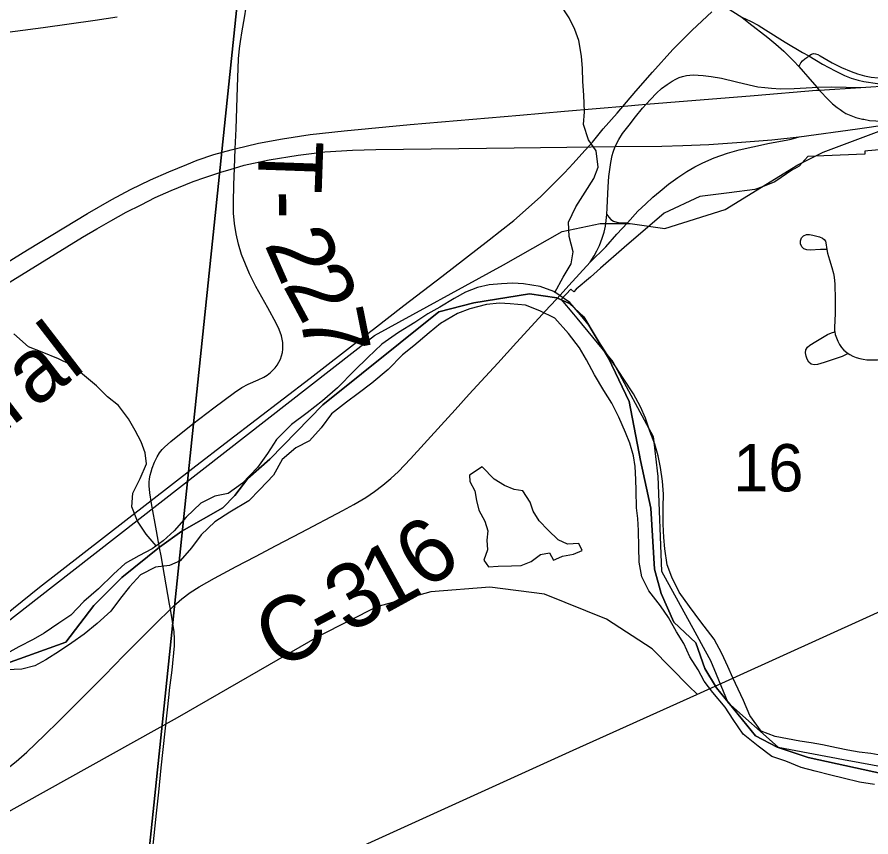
# Model space of a CAD drawing. Extents: x 0 to 34, y 0 to 22.
# Drawn here: x 5.966 to 6.722, y 17.371 to 18.097 of the extents above; entities that cross this region are included whole.
import ezdxf

# ---------------------------------------------------------------- set-up
doc = ezdxf.new("R2010")
doc.units = 0
for name, color, linetype in [('GM_X_City_Street', 7, 'Continuous'), ('GM_X_County_Road', 7, 'Continuous'), ('GM_X_County_Road_Text', 7, 'Continuous'), ('GM_X_Major_River', 7, 'Continuous'), ('GM_X_Minor_Lake', 7, 'Continuous'), ('GM_X_Minor_River', 7, 'Continuous'), ('GM_X_Rail_Line', 7, 'Continuous'), ('GM_X_Rail_Line_Text', 7, 'Continuous'), ('GM_X_Section', 7, 'Continuous'), ('GM_X_Section_Text', 7, 'Continuous'), ('GM_X_State_Route', 7, 'Continuous'), ('GM_X_Township_Road', 7, 'Continuous'), ('GM_X_Township_Road_Text', 7, 'Continuous'), ('GM_X_US_Route', 7, 'Continuous'), ('SC_Shading1', 7, 'Continuous')]:
    doc.layers.add(name, color=color, linetype=linetype)

msp = doc.modelspace()

# ---------------------------------------------------------------- linework, layer by layer
at = {"layer": 'GM_X_City_Street'}
for points in [[(6.68261, 17.89107), (6.67714, 17.89083), (6.6679, 17.89041), (6.66494, 17.89065), (6.66233, 17.8915), (6.66043, 17.8933), (6.65942, 17.8958), (6.65942, 17.89856), (6.66033, 17.90116), (6.6621, 17.90316), (6.66453, 17.90423), (6.66729, 17.90421), (6.67028, 17.90362), (6.67617, 17.90203), (6.67884, 17.90091), (6.6803, 17.89987), (6.68145, 17.89835)], [(6.68145, 17.89835), (6.68182, 17.89677), (6.68261, 17.89107)], [(6.68261, 17.89107), (6.68333, 17.88763), (6.68507, 17.88164), (6.68699, 17.87503), (6.68856, 17.86968), (6.68913, 17.86632), (6.68972, 17.86033), (6.69005, 17.84679), (6.68997, 17.83445), (6.68937, 17.82205), (6.68956, 17.81886), (6.68971, 17.81808)], [(5.94908, 17.52193), (6.00928, 17.54355), (6.034, 17.57598), (6.05869, 17.60068), (6.09198, 17.62754), (6.11197, 17.64165), (6.14824, 17.66245), (6.1588, 17.67338), (6.17022, 17.68824), (6.18965, 17.70538), (6.23654, 17.7534), (6.33939, 17.83572), (6.37026, 17.84374), (6.41941, 17.85174), (6.44369, 17.84821), (6.45506, 17.8432), (6.4677, 17.83122), (6.48945, 17.79478), (6.50784, 17.75636), (6.5177, 17.70429), (6.52683, 17.662), (6.53025, 17.60829), (6.53597, 17.58656), (6.54741, 17.56141), (6.56684, 17.54313), (6.57483, 17.52028), (6.58512, 17.50314), (6.61942, 17.46086), (6.63885, 17.45058), (6.66628, 17.44144), (6.74058, 17.42544)], [(6.74058, 17.42544), (6.66628, 17.44144), (6.63885, 17.45058), (6.61942, 17.46086), (6.58512, 17.50314), (6.57483, 17.52028), (6.56684, 17.54313), (6.54741, 17.56141), (6.53597, 17.58656), (6.53025, 17.60829), (6.52683, 17.662), (6.5177, 17.70429), (6.50784, 17.75636), (6.48945, 17.79478), (6.4677, 17.83122), (6.45506, 17.8432), (6.44369, 17.84821), (6.41941, 17.85174), (6.37026, 17.84374), (6.33939, 17.83572), (6.23654, 17.7534), (6.18965, 17.70538), (6.17022, 17.68824), (6.1588, 17.67338), (6.14824, 17.66245), (6.11197, 17.64165), (6.09198, 17.62754), (6.05869, 17.60068), (6.034, 17.57598), (6.00928, 17.54355), (5.94908, 17.52193)], [(6.70143, 17.79893), (6.69864, 17.79737), (6.69631, 17.79621), (6.68022, 17.79092), (6.67432, 17.78932), (6.67141, 17.78902), (6.66879, 17.78957), (6.6668, 17.79124), (6.6654, 17.79378), (6.66437, 17.7966), (6.66376, 17.79946), (6.66405, 17.80213), (6.66547, 17.8044), (6.66772, 17.80624), (6.67293, 17.80963), (6.68337, 17.81582), (6.68665, 17.81721), (6.68971, 17.81808)], [(6.68971, 17.81808), (6.69015, 17.81571), (6.69112, 17.81266), (6.69239, 17.80975), (6.6939, 17.80694), (6.69568, 17.80428), (6.69779, 17.80185), (6.70023, 17.79974), (6.70143, 17.79893)], [(6.70143, 17.79893), (6.7029, 17.79797), (6.70576, 17.79653), (6.70872, 17.79538), (6.71177, 17.7945), (6.71488, 17.79387), (6.71801, 17.79347), (6.72115, 17.79327), (6.72744, 17.7934), (6.72885, 17.79354)]]:
    msp.add_lwpolyline(points, dxfattribs=at)
at = {"layer": 'GM_X_County_Road'}
for points in [[(6.47331, 17.87963), (6.4769, 17.88537), (6.47915, 17.88962), (6.48147, 17.89441), (6.48393, 17.90108), (6.48557, 17.90628), (6.4867, 17.91149), (6.48748, 17.91644), (6.48789, 17.92179), (6.48834, 17.92774), (6.48913, 17.94634), (6.48983, 17.95561), (6.49146, 17.96789), (6.49266, 17.97397), (6.49351, 17.97696), (6.49545, 17.98197), (6.49576, 17.98275), (6.49859, 17.98828), (6.50192, 17.99353), (6.50763, 18.00089), (6.51326, 18.00827), (6.51959, 18.01587), (6.52282, 18.01944), (6.52652, 18.02351), (6.53179, 18.02918), (6.53641, 18.03333), (6.54141, 18.03701), (6.54574, 18.03993), (6.54893, 18.04163), (6.552, 18.04301), (6.55508, 18.04402), (6.55842, 18.0447), (6.56134, 18.04508), (6.565, 18.04529), (6.56887, 18.04518), (6.57334, 18.04481), (6.58016, 18.0439), (6.58935, 18.04234), (6.60262, 18.03924), (6.61382, 18.03653), (6.62172, 18.03494), (6.62772, 18.03409), (6.63366, 18.03351), (6.64178, 18.03319), (6.65381, 18.03335), (6.66969, 18.03428), (6.67383, 18.0344), (6.68689, 18.03477), (6.7128, 18.03414)], [(6.50622, 17.91437), (6.51539, 17.92474), (6.52241, 17.93134), (6.5288, 17.93729), (6.53518, 17.94251), (6.54263, 17.94868), (6.55084, 17.95454), (6.55891, 17.96007), (6.56572, 17.964), (6.57306, 17.96762), (6.58307, 17.97188), (6.59466, 17.97614), (6.60499, 17.97911), (6.61722, 17.98188), (6.63202, 17.98497), (6.64671, 17.98766), (6.65096, 17.98867), (6.65819, 17.99071)], [(6.48789, 17.92179), (6.48971, 17.91964), (6.49156, 17.91744), (6.49399, 17.9159), (6.49675, 17.91503), (6.49972, 17.91461), (6.5044, 17.91443), (6.50622, 17.91437)], [(6.47331, 17.87963), (6.48697, 17.89337), (6.49683, 17.90439), (6.50622, 17.91437)], [(6.44392, 17.84767), (6.45445, 17.85904), (6.47331, 17.87963)], [(6.1018, 17.57271), (6.10476, 17.57558), (6.11177, 17.58182), (6.11924, 17.58752), (6.12712, 17.59261), (6.14068, 17.60027), (6.15983, 17.61044), (6.17699, 17.61926), (6.19522, 17.6291), (6.21755, 17.64062), (6.25441, 17.66006), (6.26401, 17.66531), (6.27456, 17.67167), (6.28225, 17.67684), (6.28971, 17.68237), (6.29684, 17.68827), (6.30359, 17.69461), (6.31434, 17.70576), (6.34127, 17.73557), (6.35379, 17.7491), (6.36629, 17.76291), (6.3768, 17.77436), (6.39155, 17.7903), (6.40816, 17.80878), (6.43756, 17.84082), (6.44392, 17.84767)], [(5.84997, 17.38204), (5.86165, 17.38696), (5.87291, 17.3915), (5.89518, 17.4011), (5.91806, 17.41082), (5.92878, 17.41579), (5.93818, 17.42033), (5.94555, 17.42437), (5.95259, 17.42867), (5.9581, 17.43239), (5.96531, 17.4379), (5.97461, 17.44616), (5.99033, 17.4613), (6.00304, 17.47377), (6.01373, 17.48438), (6.02434, 17.49498), (6.04331, 17.51404), (6.06069, 17.53174), (6.08921, 17.56035), (6.1018, 17.57271)]]:
    msp.add_lwpolyline(points, dxfattribs=at)
at = {"layer": 'GM_X_Major_River'}
for points in [[(6.73445, 17.44276), (6.7216, 17.44496), (6.71139, 17.44634), (6.70118, 17.4481), (6.69136, 17.45023), (6.6789, 17.4528), (6.66869, 17.45456), (6.65886, 17.45593), (6.63694, 17.46024), (6.62453, 17.46471), (6.61461, 17.47861), (6.60886, 17.49204), (6.60416, 17.50202), (6.59946, 17.51201), (6.59514, 17.52198), (6.58973, 17.5335), (6.58282, 17.54619), (6.57104, 17.56166), (6.56111, 17.57518), (6.55193, 17.58793), (6.5454, 17.601), (6.54149, 17.6121), (6.53917, 17.62621), (6.53827, 17.6361), (6.53779, 17.64789), (6.53777, 17.66308), (6.53804, 17.67446), (6.53717, 17.68588), (6.53557, 17.69807), (6.53353, 17.70837), (6.53036, 17.7187), (6.52608, 17.73019), (6.52218, 17.74168), (6.51787, 17.75165), (6.51169, 17.76319), (6.50253, 17.77708), (6.49594, 17.78711), (6.48896, 17.79715), (6.48091, 17.80949), (6.47251, 17.82336), (6.46477, 17.83304), (6.45516, 17.8439), (6.44097, 17.85373), (6.42893, 17.85819), (6.41418, 17.86044), (6.40471, 17.86104), (6.39483, 17.86051), (6.3838, 17.85964), (6.3735, 17.85722), (6.36278, 17.85329), (6.35277, 17.84745), (6.34006, 17.83977), (6.32967, 17.83394), (6.3181, 17.82624), (6.30347, 17.81746), (6.2888, 17.80718)], [(6.72474, 17.41755), (6.71151, 17.41976), (6.69717, 17.42313), (6.68623, 17.42605), (6.67227, 17.42941), (6.65982, 17.43274), (6.64629, 17.43838), (6.63387, 17.44247), (6.62194, 17.45148), (6.60852, 17.46205), (6.59973, 17.47517), (6.59277, 17.48596), (6.5817, 17.49913), (6.57397, 17.50919), (6.56889, 17.51918), (6.56157, 17.53074), (6.55615, 17.54226), (6.54957, 17.55267), (6.54266, 17.56536), (6.53532, 17.57579), (6.525, 17.58894), (6.51884, 17.60124), (6.51649, 17.61421), (6.51643, 17.6275), (6.51602, 17.64232), (6.51552, 17.65297), (6.51423, 17.66249), (6.51383, 17.67769), (6.51368, 17.68757), (6.51319, 17.69897), (6.51152, 17.70851), (6.50837, 17.7196), (6.50443, 17.72918), (6.49867, 17.74261), (6.49251, 17.75491), (6.48519, 17.7661), (6.47717, 17.77996), (6.4699, 17.79342), (6.46369, 17.80382), (6.45413, 17.81658), (6.44193, 17.83016), (6.4288, 17.83655), (6.41602, 17.84179), (6.40238, 17.84287), (6.3929, 17.84347), (6.38149, 17.84222), (6.36659, 17.83839), (6.35587, 17.83446), (6.34085, 17.82532), (6.33079, 17.8172), (6.31724, 17.80575), (6.30718, 17.79763), (6.29434, 17.78464), (6.28002, 17.77282), (6.26803, 17.76361), (6.2576, 17.75588), (6.24445, 17.74555), (6.23505, 17.73324), (6.22491, 17.72171), (6.21262, 17.71554), (6.2006, 17.70519), (6.19306, 17.69131), (6.181, 17.67868), (6.17127, 17.66866), (6.15446, 17.65861)], [(6.2888, 17.80718), (6.27638, 17.79531), (6.26472, 17.78382), (6.24955, 17.7686), (6.23638, 17.75714), (6.22284, 17.74644), (6.20893, 17.73613), (6.19571, 17.72277), (6.18782, 17.71043), (6.1788, 17.69811), (6.16557, 17.68436), (6.15293, 17.675)], [(6.15293, 17.675), (6.14109, 17.6726), (6.12878, 17.6664), (6.11557, 17.65414), (6.10503, 17.6422), (6.09532, 17.63328), (6.08565, 17.62626), (6.07372, 17.62005), (6.06178, 17.61309), (6.0513, 17.60381), (6.03807, 17.59078), (6.02527, 17.57965), (6.01358, 17.56735), (6.00316, 17.56035), (5.99003, 17.55151), (5.98039, 17.54601), (5.96769, 17.53945), (5.95691, 17.53359)], [(6.15446, 17.65861), (6.14096, 17.65016), (6.12891, 17.63863), (6.12028, 17.62703), (6.11051, 17.61545), (6.10091, 17.61147), (6.0887, 17.60984), (6.07524, 17.60328), (6.06549, 17.59246), (6.05766, 17.58236), (6.04904, 17.57114), (6.037, 17.55999), (6.02538, 17.55074), (6.01455, 17.54299), (6.00374, 17.53561), (5.99139, 17.52789), (5.98177, 17.52278), (5.97029, 17.51961), (5.95659, 17.51915)]]:
    msp.add_lwpolyline(points, dxfattribs=at)
at = {"layer": 'GM_X_Minor_Lake'}
for points in [[(6.37767, 17.6986), (6.36636, 17.69143), (6.36669, 17.68575), (6.37117, 17.67737), (6.37262, 17.66901), (6.37482, 17.66027), (6.38005, 17.65075), (6.38263, 17.64201), (6.38181, 17.63367), (6.3825, 17.62532), (6.37903, 17.61625), (6.38314, 17.61015), (6.39185, 17.61085), (6.40358, 17.61114), (6.41228, 17.61145), (6.42101, 17.6148), (6.42938, 17.62119), (6.43733, 17.62265), (6.44069, 17.61618), (6.44564, 17.61826)], [(6.44564, 17.61826), (6.44866, 17.61953), (6.45851, 17.62136), (6.4661, 17.62471), (6.46312, 17.6308), (6.45328, 17.63012), (6.44498, 17.63397), (6.43597, 17.64276), (6.42809, 17.65078), (6.42286, 17.65954), (6.42027, 17.66753), (6.41354, 17.67743), (6.40598, 17.67863), (6.3973, 17.68211), (6.38827, 17.68786), (6.37767, 17.6986)]]:
    msp.add_lwpolyline(points, dxfattribs=at)
at = {"layer": 'GM_X_Minor_River'}
for points in [[(6.44202, 17.853), (6.4494, 17.86644), (6.4563, 17.87815), (6.45827, 17.88875), (6.45459, 17.90244), (6.45393, 17.91496), (6.46047, 17.92857), (6.46889, 17.94179), (6.47655, 17.95387), (6.48041, 17.9637), (6.47862, 17.97813), (6.47189, 17.98804), (6.46745, 18.00136), (6.4683, 18.01273), (6.46766, 18.02753), (6.46661, 18.03968), (6.46632, 18.05106), (6.46565, 18.06207), (6.46311, 18.07575), (6.45978, 18.08564), (6.45456, 18.09592), (6.44596, 18.10888)], [(6.08921, 17.62885), (6.08018, 17.63916), (6.07273, 17.65064), (6.06757, 17.66323), (6.06848, 17.67537), (6.07509, 17.68821), (6.08058, 17.70144), (6.07955, 17.71094), (6.07588, 17.72086), (6.07068, 17.7308), (6.06473, 17.74112), (6.05577, 17.753), (6.04599, 17.76071), (6.03623, 17.77033), (6.02382, 17.78073), (6.01367, 17.78882), (6.00272, 17.79427), (5.98836, 17.80013), (5.97626, 17.80483), (5.96311, 17.81639)]]:
    msp.add_lwpolyline(points, dxfattribs=at)
at = {"layer": 'GM_X_Rail_Line'}
msp.add_line((6.56202, 17.50105), (6.56202, 17.50105), dxfattribs=at)
for points in [[(5.94727, 17.56139), (5.98597, 17.59224), (6.12161, 17.69738), (6.1537, 17.72221), (6.22532, 17.7772), (6.26915, 17.81096), (6.28134, 17.82054), (6.30844, 17.84142), (6.34201, 17.86713), (6.38372, 17.89942), (6.39359, 17.90712), (6.40554, 17.91669), (6.42133, 17.93037), (6.42967, 17.93782), (6.44172, 17.94976), (6.45045, 17.95865), (6.4581, 17.96689), (6.4658, 17.97558), (6.47543, 17.98599), (6.48476, 17.99755), (6.497, 18.01161), (6.51378, 18.03106), (6.52834, 18.04784), (6.54631, 18.06774), (6.56339, 18.08496), (6.58086, 18.10125)], [(5.45041, 17.18091), (5.46894, 17.18251), (5.557, 17.24946), (5.69693, 17.35834), (5.99732, 17.59283), (6.28231, 17.81477), (6.39655, 17.87736), (6.44837, 17.9068), (6.48198, 17.91381), (6.50859, 17.91382), (6.5394, 17.90962), (6.59262, 17.92644), (6.65705, 17.9657), (6.67945, 17.97692), (6.73127, 17.99655)], [(5.64545, 16.98321), (5.66714, 17.00105), (5.69917, 17.03535), (5.73998, 17.08975), (5.75979, 17.11518), (5.77861, 17.13707), (5.807, 17.16437), (5.83351, 17.18516), (5.85342, 17.19808), (5.87067, 17.20774), (5.90241, 17.22242), (5.95258, 17.24174), (6.04277, 17.27427), (6.14478, 17.31113), (6.17129, 17.32049), (6.21811, 17.33892), (6.45831, 17.44794), (6.56772, 17.49722), (6.86452, 17.63205)], [(6.56749, 17.49775), (6.56079, 17.50426), (6.52813, 17.53777), (6.48765, 17.56396), (6.43283, 17.58607), (6.38437, 17.59217), (6.33231, 17.58822), (6.28453, 17.57479), (6.23371, 17.54914), (6.10764, 17.47677), (5.85482, 17.33611), (5.72919, 17.26593), (5.64982, 17.22157), (5.59407, 17.19783), (5.47414, 17.16035), (5.39663, 17.13975)]]:
    msp.add_lwpolyline(points, dxfattribs=at)
at = {"layer": 'GM_X_Section'}
for points in [[(5.13301, 18.35974), (6.17707, 18.26412), (6.07115, 17.24621), (5.04874, 17.32193)], [(6.17707, 18.26412), (7.17505, 18.16824), (7.08554, 17.16561), (6.07115, 17.24621)]]:
    msp.add_lwpolyline(points, close=True, dxfattribs=at)
at = {"layer": 'GM_X_State_Route'}
for points in [[(5.87826, 17.83089), (5.97517, 17.8906), (6.02829, 17.92283), (6.04982, 17.93518), (6.06637, 17.94391), (6.08411, 17.95264), (6.10027, 17.9597), (6.11632, 17.96624), (6.12543, 17.96996), (6.14032, 17.97484), (6.15546, 17.9792), (6.15914, 17.98009), (6.17984, 17.9851), (6.20102, 17.98896), (6.22553, 17.99268), (6.25543, 17.99601), (6.31408, 18.0014), (6.3694, 18.00615), (6.41085, 18.00974), (6.45063, 18.01334), (6.50658, 18.01795), (6.51586, 18.0189), (6.52282, 18.01944), (6.54105, 18.02086), (6.61824, 18.02719), (6.67354, 18.03182), (6.67594, 18.03196), (6.7128, 18.03414), (6.73961, 18.03586)], [(6.65819, 17.99071), (6.7098, 17.99763), (6.7608, 18.00503)], [(6.45268, 17.9815), (6.49545, 17.98197), (6.53661, 17.98242), (6.5552, 17.98282), (6.57838, 17.98381), (6.60715, 17.98579), (6.63388, 17.98808), (6.65819, 17.99071)], [(6.15544, 17.96199), (6.15848, 17.96288), (6.16703, 17.9654), (6.18923, 17.97033), (6.21488, 17.97444), (6.23362, 17.97665)], [(6.23362, 17.97665), (6.23855, 17.97724), (6.26289, 17.97888), (6.28344, 17.97947), (6.40592, 17.98098), (6.45268, 17.9815)], [(5.87672, 17.81131), (5.89031, 17.81968), (6.02385, 17.90176), (6.03666, 17.90934), (6.04899, 17.91624), (6.06264, 17.92397), (6.07579, 17.93038), (6.08829, 17.93679), (6.10242, 17.94304), (6.12199, 17.9511), (6.13218, 17.95471), (6.14632, 17.95932), (6.15544, 17.96199)]]:
    msp.add_lwpolyline(points, dxfattribs=at)
at = {"layer": 'GM_X_Township_Road'}
for points in [[(6.09221, 17.627), (6.08941, 17.64197), (6.08498, 17.66635), (6.08355, 17.67559), (6.083, 17.68185), (6.08307, 17.68502), (6.08338, 17.68818), (6.08393, 17.6913), (6.08472, 17.69437), (6.08573, 17.69737), (6.08765, 17.7027), (6.09, 17.70754), (6.09221, 17.71113), (6.09456, 17.71403), (6.09663, 17.71611), (6.10202, 17.72094), (6.12151, 17.73669), (6.14016, 17.75093), (6.1584, 17.76433), (6.16503, 17.76875), (6.17056, 17.77179), (6.17954, 17.77552), (6.18452, 17.77787), (6.18742, 17.77967), (6.19024, 17.78208), (6.19244, 17.78412), (6.19445, 17.78635), (6.19625, 17.78873), (6.1978, 17.79129), (6.19909, 17.79397), (6.20012, 17.79678), (6.20081, 17.79967), (6.20122, 17.80265), (6.2013, 17.80563), (6.20112, 17.8086), (6.20067, 17.81159), (6.19999, 17.81452), (6.19802, 17.82027), (6.19547, 17.82585), (6.18812, 17.83941), (6.17736, 17.85823), (6.17184, 17.86935), (6.16807, 17.87787), (6.1648, 17.88661), (6.16216, 17.89556), (6.16008, 17.90467), (6.15857, 17.91389), (6.15771, 17.92321), (6.15752, 17.93254), (6.15791, 17.94806), (6.15848, 17.96288), (6.15914, 17.98009), (6.15981, 17.99759), (6.16103, 18.03448), (6.16206, 18.05947), (6.16291, 18.06876), (6.16376, 18.07492), (6.16531, 18.08423), (6.16738, 18.09597), (6.16879, 18.10524)], [(6.65784, 18.05268), (6.65846, 18.05383), (6.65959, 18.05593), (6.66114, 18.0579), (6.66307, 18.05958), (6.6658, 18.06147), (6.66672, 18.0621)], [(6.66672, 18.0621), (6.66916, 18.06361), (6.67097, 18.06424), (6.67269, 18.06411), (6.6747, 18.0634), (6.67675, 18.06227), (6.68739, 18.0561), (6.69563, 18.05191), (6.70411, 18.04825), (6.70992, 18.04623), (6.71585, 18.04462), (6.72188, 18.04345), (6.72798, 18.04275), (6.73405, 18.04241), (6.74025, 18.04222), (6.74811, 18.04191), (6.75117, 18.04162), (6.75347, 18.04126), (6.76389, 18.03918), (6.76988, 18.03798)], [(6.1018, 17.57271), (6.10109, 17.57711), (6.0935, 17.61992), (6.09221, 17.627)], [(6.10108, 17.50117), (6.10325, 17.51885), (6.10541, 17.5404), (6.10548, 17.54652), (6.10499, 17.55261), (6.1018, 17.57271)], [(6.08572, 17.35187), (6.08572, 17.35475), (6.08616, 17.36146), (6.08933, 17.39238), (6.09151, 17.41084), (6.09363, 17.43244), (6.1006, 17.49724), (6.10108, 17.50117)]]:
    msp.add_lwpolyline(points, dxfattribs=at)
at = {"layer": 'GM_X_US_Route'}
msp.add_line((6.6074, 18.0964), (6.61373, 18.09144), dxfattribs=at)
for points in [[(6.59379, 18.10486), (6.6074, 18.0964)], [(5.4179, 18.00691), (5.48173, 18.01572), (5.58937, 18.03095), (5.62855, 18.03648), (5.63226, 18.03701), (5.70315, 18.04717), (5.74931, 18.05353), (5.78621, 18.0587), (5.84024, 18.06668), (5.88455, 18.07321), (5.90776, 18.07639), (5.92148, 18.07827), (5.94609, 18.08156), (5.98912, 18.0872), (6.0352, 18.09383), (6.05457, 18.09664)], [(6.6074, 18.0964), (6.61519, 18.09277), (6.6219, 18.08929), (6.62843, 18.08514), (6.64589, 18.07446), (6.66127, 18.06533), (6.66672, 18.0621), (6.67885, 18.05491), (6.68994, 18.04895), (6.69842, 18.04484), (6.70426, 18.04249), (6.71027, 18.04062), (6.71546, 18.03943), (6.73961, 18.03586)], [(6.61373, 18.09144), (6.63035, 18.07843), (6.63763, 18.07254), (6.64461, 18.0663), (6.65346, 18.05749), (6.65784, 18.05268)], [(6.65784, 18.05268), (6.66186, 18.04827), (6.66594, 18.04354), (6.67383, 18.0344), (6.67594, 18.03196), (6.67694, 18.0308), (6.6833, 18.02411), (6.68782, 18.01978), (6.69191, 18.0165), (6.69436, 18.01467), (6.69689, 18.01287), (6.69958, 18.0113), (6.70238, 18.00994), (6.70827, 18.00784), (6.71431, 18.00626), (6.71534, 18.00608)], [(6.71534, 18.00608), (6.72046, 18.00517), (6.72593, 18.00463), (6.73019, 18.00437), (6.73498, 18.00443), (6.74761, 18.00453), (6.7608, 18.00503)]]:
    msp.add_lwpolyline(points, dxfattribs=at)
at = {"layer": 'SC_Shading1'}
msp.add_lwpolyline([(6.8221, 17.98717), (6.71908, 17.97813), (6.7164, 17.97789), (6.71617, 17.97537), (6.68004, 17.97372), (6.6657, 17.97307), (6.66045, 17.96731), (6.6581, 17.96474), (6.654, 17.9624), (6.65251, 17.96155), (6.63679, 17.95078), (6.62559, 17.94644), (6.61897, 17.94386), (6.59621, 17.94109), (6.57018, 17.93792), (6.53881, 17.92294), (6.50344, 17.89272), (6.48248, 17.87428), (6.4735, 17.86638), (6.46084, 17.85579), (6.4587, 17.85345), (6.456, 17.85593), (6.4476, 17.8468), (6.45853, 17.83359), (6.46145, 17.83005), (6.49331, 17.79153), (6.52889, 17.72548), (6.5331, 17.6901), (6.53624, 17.60637), (6.56572, 17.55262), (6.57495, 17.5358), (6.57966, 17.52723), (6.58465, 17.51515), (6.59498, 17.49021), (6.63967, 17.45063), (6.69752, 17.43991), (6.76328, 17.42772)], dxfattribs=at)

# ---------------------------------------------------------------- texts
at = {"layer": 'GM_X_County_Road_Text'}
for s, rotation, p in [('6', 35.86319, (6.32722, 17.58841)), ('1', 28.74359, (6.29002, 17.56746)), ('3', 28.0069, (6.25842, 17.55065)), ('C', 27.91441, (6.19648, 17.51782)), ('-', 27.93625, (6.23773, 17.53968))]:
    msp.add_text(s, height=0.05682, rotation=rotation, dxfattribs=at).set_placement(p)
at = {"layer": 'GM_X_Rail_Line_Text'}
msp.add_text('Indiana & Ohio Central', height=0.0566288, rotation=37.6342, dxfattribs=at).set_placement((5.42152, 17.31796))
at = {"layer": 'GM_X_Section_Text'}
msp.add_text('16', height=0.041856, rotation=0.00001, dxfattribs=at).set_placement((6.5997, 17.67693))
at = {"layer": 'GM_X_Township_Road_Text'}
for s, rotation, p in [('T', 267.9998, (6.18042, 17.98834)), ('-', 270.94434, (6.17891, 17.94276)), ('2', 293.79757, (6.18455, 17.89566)), ('2', 298.25748, (6.20068, 17.85956)), ('7', 281.44401, (6.21562, 17.83311))]:
    msp.add_text(s, height=0.05682, rotation=rotation, dxfattribs=at).set_placement(p)

doc.saveas('drawing.dxf')
